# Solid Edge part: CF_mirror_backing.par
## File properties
Author: Owner
Template: Iso Part.par
Last saved by: Lee
Revision: 39
Application: Solid Edge
Material: Silver
Face Style: Silver
Fill Style: ANSI31(Iron)
Virtual Style: Silver
Coef. of Thermal Exp: 1e-05
Thermal Conductivity: 419.0
Specific Heat: 234.0
Modulus of Elasticity: 75842327000.0
Poisson's Ratio: 0.38
Yield Stress: 303369308.0
Ultimate Stress: 344737850.0
Elongation: 0.0
Density: 1.050e+004 kg/m^3
Accuracy: 0.990
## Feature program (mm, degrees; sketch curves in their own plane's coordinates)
sketch for "unnamed RevolvedProtrusion 1" plane through (0, 0, 0) normal (0, -1, 0) x-axis (1, 0, 0)
  line (0, -86.784) -> (1000, -86.784)
  line (1000, 637.5873) -> (1000, -86.784)
  arc centre (0, 1103) radius 1103 from (0, 0) to (1000, 637.5873) ccw
  line (0, 0) -> (0, -86.784)
revolve "unnamed RevolvedProtrusion 1" add full turn 360 deg
thinwall "Thinwall_1"  Thickness = 1.5 mm
sketch for "unnamed Cutout 1" #1 plane through (0, 0, -86.784) normal (0, 0, -1) x-axis (-1, 0, 0)
  line (300, 275) -> (300, -275)
  line (300, -275) -> (-300, -275)
  line (-300, -275) -> (-300, 275)
  line (-300, 275) -> (300, 275)
sketch for "unnamed Cutout 1" #2 plane through (0, 0, -86.784) normal (0, 0, -1) x-axis (-1, 0, 0)
  circle centre (0, 0) radius 1152.023
extrude "unnamed Cutout 1" cut finite 850 along -normal
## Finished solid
Body 1: solid body, 6 faces, 12 edges, 8 vertices.
  Faces by surface: plane 4, sphere 2
  Edges by curve: circle 8, line 4
Bounding box of the edges (mm; curved faces can reach further): 600.000 x 550.000 x 44.542, from (-300, -275, 33.2826) to (300, 275, 77.8249).
Spherical faces by radius (mm): R1103 x1, R1104.5 x1
Planar faces by outward normal: +x 1, +y 1, -x 1, -y 1
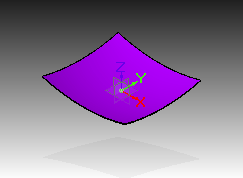
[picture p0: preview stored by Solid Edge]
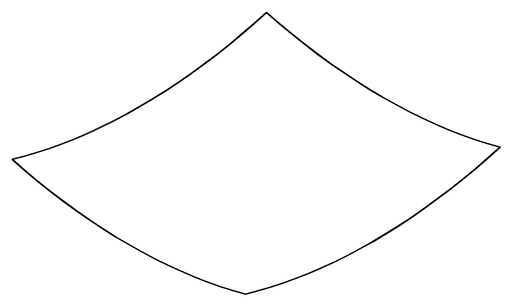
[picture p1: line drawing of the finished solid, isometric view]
